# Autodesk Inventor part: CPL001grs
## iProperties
Shininess: 3
Length Units: 11272
Angle Units: 11279
Time Units: 11290
Mass Units: 11286
Length Display Precision: 3
Angle Display Precision: 2
Compacted: True
Company: Autodesk
Manager: Lebovitz
Created: 2001-05
Part Number: CPL001grs
Document SubType Name: Modeling
Designer: The PD Team
Project: Inventor Samples
Description: the box base
Checked By: The PD Team
Density: 0.0
Volumn: 0.0
Area: 0.0
PropertySet Name: Model Information
Control State: 0
Master: False
Checked Out: False
Title: box base
Subject: cross part loop example
Author: The PD Team
Revision Number: A
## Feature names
1. Extrusion1
2. Hole1
3. Fillet2
4. Shell1
5. Fillet3
